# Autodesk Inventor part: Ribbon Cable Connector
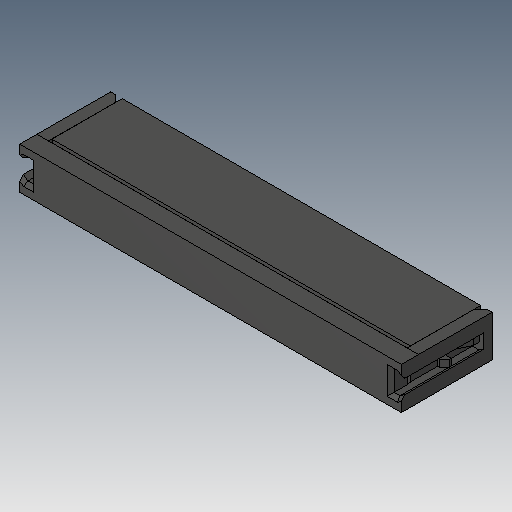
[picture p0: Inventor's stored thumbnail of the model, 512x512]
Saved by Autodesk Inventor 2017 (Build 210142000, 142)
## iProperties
Created: 2006-07
Part Number: Ribbon Cable Connector
Material: Generic
Document SubType Name: Modeling
Designer: DanielSeverino
Density: 1 g/cm^3
Appearance: Default
Author: DanielSeverino
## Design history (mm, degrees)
feature "Solid1"
body "Solid2"
